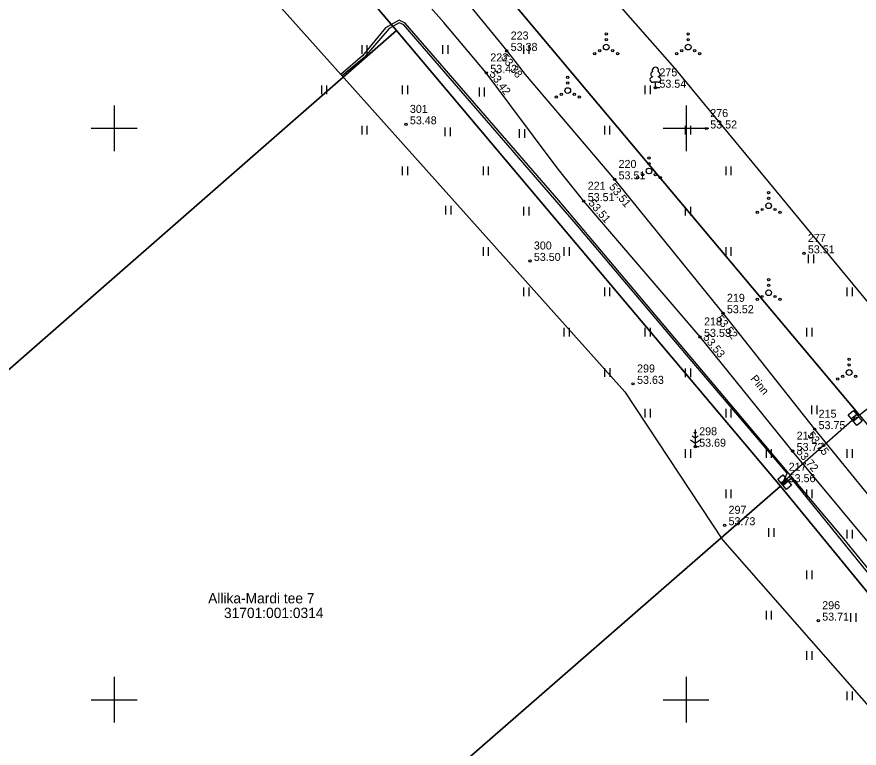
# Model space of a CAD drawing. Extents: x 538599 to 541973, y 6559689 to 6564516.
# Drawn here: x 540391.5 to 540465.1, y 6561345.8 to 6561409.8 of the extents above; entities that cross this region are included whole.
import ezdxf

# ---------------------------------------------------------------- set-up
doc = ezdxf.new("R2010")
doc.units = 0
for name, color, linetype in [('ELRAJATISMP', 7, 'Continuous'), ('HALJASTUS', 7, 'Continuous'), ('KORGUS-EH2000', 7, 'Continuous'), ('KPKAABEL', 7, 'Continuous'), ('MOOTKORG-EH2000', 7, 'Continuous'), ('MOOTMPUNKT', 7, 'Continuous'), ('MOOTNR', 7, 'Continuous'), ('MOOTPIIR', 7, 'Continuous'), ('MPKAABEL', 7, 'Continuous'), ('PIIR', 7, 'Continuous'), ('PUU', 7, 'Continuous'), ('TEE', 7, 'Continuous'), ('VORK', 7, 'Continuous')]:
    doc.layers.add(name, color=color, linetype=linetype)

msp = doc.modelspace()

# ---------------------------------------------------------------- linework, layer by layer
at = {"layer": 'ELRAJATISMP'}
for p, q in [((540464.943, 6561374.955), (540464.48, 6561374.578)), ((540465.114, 6561374.744), (540464.651, 6561374.367)), ((540458.768, 6561369.33), (540458.309, 6561368.949)), ((540458.941, 6561369.121), (540458.482, 6561368.74))]:
    msp.add_line(p, q, dxfattribs=at)
for points in [[(540464.652, 6561375.313), (540465.405, 6561374.386), (540464.942, 6561374.009), (540464.189, 6561374.936)], [(540458.473, 6561369.685), (540459.236, 6561368.766), (540458.777, 6561368.385), (540458.014, 6561369.304)]]:
    msp.add_lwpolyline(points, close=True, dxfattribs=at)
at = {"layer": 'HALJASTUS'}
for p, q in [((540421.648, 6561407.28), (540421.648, 6561406.519)), ((540422.103, 6561407.28), (540422.103, 6561406.519)), ((540428.719, 6561407.28), (540428.719, 6561406.519)), ((540429.175, 6561407.28), (540429.175, 6561406.519)), ((540435.791, 6561407.28), (540435.791, 6561406.519)), ((540436.246, 6561407.28), (540436.246, 6561406.519)), ((540418.113, 6561403.744), (540418.113, 6561402.983)), ((540418.568, 6561403.744), (540418.568, 6561402.983)), ((540425.184, 6561403.744), (540425.184, 6561402.983)), ((540425.639, 6561403.744), (540425.639, 6561402.983)), ((540431.902, 6561403.559), (540431.902, 6561402.797)), ((540432.357, 6561403.559), (540432.357, 6561402.797)), ((540446.397, 6561403.744), (540446.397, 6561402.983)), ((540446.852, 6561403.744), (540446.852, 6561402.983)), ((540421.648, 6561400.209), (540421.648, 6561399.447)), ((540422.103, 6561400.209), (540422.103, 6561399.447)), ((540428.921, 6561400.079), (540428.921, 6561399.318)), ((540429.376, 6561400.079), (540429.376, 6561399.318)), ((540435.422, 6561399.934), (540435.422, 6561399.173)), ((540435.877, 6561399.934), (540435.877, 6561399.173)), ((540442.862, 6561400.209), (540442.862, 6561399.447)), ((540443.317, 6561400.209), (540443.317, 6561399.447)), ((540449.933, 6561400.209), (540449.933, 6561399.447)), ((540450.388, 6561400.209), (540450.388, 6561399.447)), ((540425.184, 6561396.673), (540425.184, 6561395.912)), ((540425.639, 6561396.673), (540425.639, 6561395.912)), ((540432.255, 6561396.673), (540432.255, 6561395.912)), ((540432.71, 6561396.673), (540432.71, 6561395.912)), ((540453.468, 6561396.673), (540453.468, 6561395.912)), ((540453.923, 6561396.673), (540453.923, 6561395.912)), ((540428.983, 6561393.223), (540428.983, 6561392.462)), ((540429.438, 6561393.223), (540429.438, 6561392.462)), ((540435.791, 6561393.138), (540435.791, 6561392.376)), ((540436.246, 6561393.138), (540436.246, 6561392.376)), ((540449.933, 6561393.138), (540449.933, 6561392.376)), ((540450.388, 6561393.138), (540450.388, 6561392.376)), ((540432.255, 6561389.602), (540432.255, 6561388.841)), ((540432.71, 6561389.602), (540432.71, 6561388.841)), ((540439.326, 6561389.602), (540439.326, 6561388.841)), ((540439.781, 6561389.602), (540439.781, 6561388.841)), ((540453.468, 6561389.602), (540453.468, 6561388.841)), ((540453.923, 6561389.602), (540453.923, 6561388.841)), ((540460.691, 6561388.968), (540460.691, 6561388.207)), ((540461.146, 6561388.968), (540461.146, 6561388.207)), ((540435.791, 6561386.066), (540435.791, 6561385.305)), ((540436.246, 6561386.066), (540436.246, 6561385.305)), ((540442.862, 6561386.066), (540442.862, 6561385.305)), ((540443.317, 6561386.066), (540443.317, 6561385.305)), ((540464.075, 6561386.066), (540464.075, 6561385.305)), ((540464.53, 6561386.066), (540464.53, 6561385.305)), ((540439.326, 6561382.531), (540439.326, 6561381.77)), ((540439.781, 6561382.531), (540439.781, 6561381.77)), ((540446.397, 6561382.531), (540446.397, 6561381.77)), ((540446.852, 6561382.531), (540446.852, 6561381.77)), ((540460.539, 6561382.531), (540460.539, 6561381.77)), ((540460.994, 6561382.531), (540460.994, 6561381.77)), ((540442.882, 6561379.016), (540442.882, 6561378.255)), ((540443.338, 6561379.016), (540443.338, 6561378.255)), ((540449.933, 6561378.995), (540449.933, 6561378.234)), ((540450.388, 6561378.995), (540450.388, 6561378.234)), ((540446.397, 6561375.46), (540446.397, 6561374.699)), ((540446.852, 6561375.46), (540446.852, 6561374.699)), ((540453.468, 6561375.46), (540453.468, 6561374.699)), ((540453.923, 6561375.46), (540453.923, 6561374.699)), ((540460.981, 6561375.739), (540460.981, 6561374.977)), ((540461.436, 6561375.739), (540461.436, 6561374.977)), ((540449.933, 6561371.924), (540449.933, 6561371.163)), ((540450.388, 6561371.924), (540450.388, 6561371.163)), ((540457.004, 6561371.924), (540457.004, 6561371.163)), ((540457.459, 6561371.924), (540457.459, 6561371.163)), ((540464.075, 6561371.924), (540464.075, 6561371.163)), ((540464.53, 6561371.924), (540464.53, 6561371.163)), ((540453.468, 6561368.389), (540453.468, 6561367.628)), ((540453.923, 6561368.389), (540453.923, 6561367.628)), ((540460.539, 6561368.389), (540460.539, 6561367.628)), ((540460.994, 6561368.389), (540460.994, 6561367.628)), ((540457.224, 6561365.014), (540457.224, 6561364.253)), ((540457.679, 6561365.014), (540457.679, 6561364.253)), ((540464.075, 6561364.853), (540464.075, 6561364.092)), ((540464.53, 6561364.853), (540464.53, 6561364.092)), ((540460.539, 6561361.318), (540460.539, 6561360.557)), ((540460.994, 6561361.318), (540460.994, 6561360.557)), ((540457.004, 6561357.782), (540457.004, 6561357.021)), ((540457.459, 6561357.782), (540457.459, 6561357.021)), ((540464.388, 6561357.579), (540464.388, 6561356.817)), ((540464.843, 6561357.579), (540464.843, 6561356.817)), ((540460.539, 6561354.247), (540460.539, 6561353.486)), ((540460.994, 6561354.247), (540460.994, 6561353.486)), ((540464.075, 6561350.711), (540464.075, 6561349.95)), ((540464.53, 6561350.711), (540464.53, 6561349.95))]:
    msp.add_line(p, q, dxfattribs=at)
for centre, radius in [((540443.021, 6561408.263), 0.1), ((540443.021, 6561407.763), 0.1), ((540450.186, 6561408.263), 0.1), ((540450.186, 6561407.763), 0.1), ((540443.021, 6561407.113), 0.25), ((540450.186, 6561407.113), 0.25), ((540442.021, 6561406.538), 0.1), ((540442.456, 6561406.788), 0.1), ((540443.586, 6561406.788), 0.1), ((540444.021, 6561406.538), 0.1), ((540449.186, 6561406.538), 0.1), ((540449.621, 6561406.788), 0.1), ((540450.751, 6561406.788), 0.1), ((540451.186, 6561406.538), 0.1), ((540439.66, 6561404.457), 0.1), ((540439.66, 6561403.307), 0.25), ((540439.66, 6561403.957), 0.1), ((540438.66, 6561402.732), 0.1), ((540439.095, 6561402.982), 0.1), ((540440.225, 6561402.982), 0.1), ((540440.66, 6561402.732), 0.1), ((540446.762, 6561397.416), 0.1), ((540446.762, 6561396.916), 0.1), ((540446.762, 6561396.266), 0.25), ((540445.762, 6561395.691), 0.1), ((540446.197, 6561395.941), 0.1), ((540447.327, 6561395.941), 0.1), ((540447.762, 6561395.691), 0.1), ((540457.224, 6561394.371), 0.1), ((540457.224, 6561393.871), 0.1), ((540457.224, 6561393.221), 0.25), ((540456.224, 6561392.646), 0.1), ((540456.659, 6561392.896), 0.1), ((540457.789, 6561392.896), 0.1), ((540458.224, 6561392.646), 0.1), ((540457.224, 6561386.76), 0.1), ((540457.224, 6561385.61), 0.25), ((540457.224, 6561386.26), 0.1), ((540456.224, 6561385.035), 0.1), ((540456.659, 6561385.285), 0.1), ((540457.789, 6561385.285), 0.1), ((540458.224, 6561385.035), 0.1), ((540464.263, 6561379.783), 0.1), ((540464.263, 6561379.283), 0.1), ((540463.698, 6561378.308), 0.1), ((540464.263, 6561378.633), 0.25), ((540464.828, 6561378.308), 0.1), ((540463.263, 6561378.058), 0.1)]:
    msp.add_circle(centre, radius, dxfattribs=at)
at = {"layer": 'KORGUS-EH2000'}
for centre in [(540434.319, 6561406.773), (540432.536, 6561404.858), (540425.505, 6561400.353), (540451.769, 6561399.986), (540443.752, 6561395.534), (540441.058, 6561393.627), (540460.306, 6561389.06), (540436.345, 6561388.398), (540453.227, 6561383.82), (540451.227, 6561381.751), (540445.37, 6561377.639), (540461.243, 6561373.674), (540459.324, 6561371.761), (540453.37, 6561365.268), (540461.559, 6561356.917)]:
    msp.add_circle(centre, 0.1, dxfattribs=at)
at = {"layer": 'KPKAABEL'}
msp.add_lwpolyline([(540612.707, 6561251.641), (540589.754, 6561235.922), (540575.113, 6561226.32), (540574.309, 6561226.488), (540572.813, 6561227.652), (540566.988, 6561234.121), (540563.285, 6561239.03), (540553.802, 6561251.292), (540538.41, 6561271.219), (540529.488, 6561282.512), (540526.272, 6561286.879), (540510.559, 6561306.203), (540484.617, 6561338.574), (540463.547, 6561364.405), (540438.892, 6561393.697), (540425.441, 6561409.211), (540424.922, 6561409.461), (540423.725, 6561408.808), (540421.719, 6561406.34), (540419.82, 6561404.72)], dxfattribs=at)
at = {"layer": 'MOOTMPUNKT'}
for centre in [(540434.319, 6561406.773), (540432.536, 6561404.858), (540447.324, 6561403.552), (540425.505, 6561400.353), (540451.769, 6561399.986), (540443.752, 6561395.534), (540441.058, 6561393.627), (540460.306, 6561389.06), (540436.345, 6561388.398), (540453.227, 6561383.82), (540451.227, 6561381.751), (540445.37, 6561377.639), (540464.797, 6561374.661), (540461.243, 6561373.674), (540450.802, 6561372.138), (540459.324, 6561371.761), (540458.625, 6561369.035), (540453.37, 6561365.268), (540461.559, 6561356.917)]:
    msp.add_circle(centre, 0.1, dxfattribs=at)
at = {"layer": 'MOOTPIIR'}
for points in [[(540611.814, 6561347.628), (540600.551, 6561344.045), (540588.991, 6561338.307), (540579.507, 6561329.749), (540567.369, 6561324.711), (540557.296, 6561315.504), (540537.549, 6561303.29), (540525.23, 6561316.048), (540500.22, 6561345.282), (540476.488, 6561371.995), (540449.028, 6561405.277), (540428.792, 6561428.292), (540413.022, 6561448.218), (540405.096, 6561459.889), (540393.809, 6561473.145)], [(540384.887, 6561443.845), (540403.973, 6561422.469), (540424.304, 6561399.698), (540444.636, 6561376.927), (540453.177, 6561363.987), (540470.995, 6561343.689), (540492.689, 6561318.976), (540511.766, 6561294.341), (540521.974, 6561279.181), (540525.589, 6561267.954), (540536.495, 6561252.794), (540542.772, 6561231.926), (540526.603, 6561219.05), (540510.624, 6561213.468), (540498.26, 6561199.196), (540484.564, 6561192.98), (540479.618, 6561185.622), (540478.413, 6561178.328), (540490.461, 6561165.832), (540493.58, 6561162.597), (540531.105, 6561187.906), (540582.869, 6561222.817), (540621.742, 6561247.747)]]:
    msp.add_lwpolyline(points, dxfattribs=at)
at = {"layer": 'MPKAABEL'}
for points in [[(540496.217, 6561323.662), (540475.169, 6561349.87), (540465.845, 6561361.182), (540459.234, 6561369.371), (540458.445, 6561368.895), (540458.855, 6561369.82), (540450.374, 6561379.812), (540440.394, 6561391.62), (540426.571, 6561407.606), (540425.316, 6561409.047), (540424.926, 6561409.234), (540424.031, 6561408.75), (540421.855, 6561406.207), (540419.931, 6561404.596)], [(540464.749, 6561374.646), (540459.18, 6561369.75), (540458.445, 6561368.895)]]:
    msp.add_lwpolyline(points, dxfattribs=at)
at = {"layer": 'PIIR'}
for points in [[(540491.21, 6561183.5), (540566.07, 6561233.36), (540528.84, 6561281.85), (540494.34, 6561324.62), (540458.27, 6561368.69), (540424.68, 6561408.57), (540384.55, 6561455.73), (540346.17, 6561499.11), (540330.12, 6561517.14), (540337.36, 6561523.32), (540348.28, 6561532.96), (540364.11, 6561514.94), (540353.14, 6561505.27), (540391.51, 6561461.86), (540431.74, 6561414.74), (540465.17, 6561374.89), (540501.31, 6561330.86), (540535.92, 6561287.97), (540573.77, 6561238.75), (540640.63, 6561283.66), (540646.74, 6561272.89), (540499, 6561174.36)], [(540431.74, 6561414.74), (540500.82, 6561475.34), (540537.11, 6561431.06), (540465.17, 6561374.89)], [(540309.49, 6561390.29), (540384.55, 6561455.73), (540424.68, 6561408.57), (540350.66, 6561343.77)], [(540350.66, 6561343.77), (540424.68, 6561408.57), (540458.27, 6561368.69), (540384.73, 6561304.57)], [(540384.73, 6561304.57), (540458.27, 6561368.69), (540494.34, 6561324.62), (540422.29, 6561261.69)]]:
    msp.add_lwpolyline(points, close=True, dxfattribs=at)
at = {"layer": 'PUU'}
for p, q in [((540447.564, 6561404.027), (540447.084, 6561404.027)), ((540447.324, 6561403.552), (540447.324, 6561404.027)), ((540447.704, 6561403.552), (540447.324, 6561403.552)), ((540450.802, 6561373.288), (540450.678, 6561373.371)), ((540450.802, 6561373.638), (540450.802, 6561372.138)), ((540450.926, 6561373.371), (540450.802, 6561373.288)), ((540450.378, 6561372.727), (540450.802, 6561372.445)), ((540450.802, 6561372.888), (540450.535, 6561373.066)), ((540451.069, 6561373.066), (540450.802, 6561372.888)), ((540450.802, 6561372.445), (540451.226, 6561372.727)), ((540451.162, 6561372.138), (540450.802, 6561372.138))]:
    msp.add_line(p, q, dxfattribs=at)
for centre, radius, start, end in [((540447.154, 6561404.725), 0.233, 109.02174, 253.14154), ((540447.324, 6561405.072), 0.277, 332.5799, 207.4201), ((540447.494, 6561404.725), 0.233, 286.85082, 70.98591), ((540447.087, 6561404.264), 0.238, 90.0016, 269.3953), ((540447.561, 6561404.264), 0.238, 270.6047, 89.9984)]:
    msp.add_arc(centre, radius, start, end, dxfattribs=at)
at = {"layer": 'TEE'}
for points in [[(540488.154, 6561336.579), (540478.587, 6561348.431), (540467.854, 6561361.491), (540459.324, 6561371.761), (540451.227, 6561381.751), (540441.058, 6561393.627), (540438.742, 6561396.541), (540432.536, 6561404.858), (540428.826, 6561409.256), (540422.187, 6561416.809), (540412.686, 6561428.773), (540402.743, 6561440.044), (540395.606, 6561447.094), (540392.506, 6561450.435), (540382.51, 6561461.307)], [(540388.6, 6561459.282), (540394.606, 6561452.944), (540404.957, 6561441.5), (540414.409, 6561430.917), (540424.761, 6561418.487), (540434.319, 6561406.773), (540435.946, 6561404.714), (540443.752, 6561395.534), (540453.227, 6561383.82), (540461.243, 6561373.674), (540469.957, 6561362.956), (540476.197, 6561354.987), (540480.237, 6561350.173), (540490.343, 6561338.333)]]:
    msp.add_lwpolyline(points, dxfattribs=at)
at = {"layer": 'VORK'}
for p, q in [((540400, 6561402), (540400, 6561398)), ((540450, 6561402), (540450, 6561398)), ((540398, 6561400), (540402, 6561400)), ((540448, 6561400), (540452, 6561400)), ((540400, 6561352), (540400, 6561348)), ((540450, 6561352), (540450, 6561348)), ((540398, 6561350), (540402, 6561350)), ((540448, 6561350), (540452, 6561350))]:
    msp.add_line(p, q, dxfattribs=at)

# ---------------------------------------------------------------- texts
at = {"layer": 'KORGUS-EH2000'}
for s, rotation, p in [('53.38', 308.31584, (540433.771, 6561406.169)), ('53.42', 306.73046, (540432.771, 6561404.716)), ('53.51', 308.96805, (540443.226, 6561394.848)), ('53.51', 310.57228, (540441.424, 6561393.431)), ('53.52', 308.31103, (540452.583, 6561383.313)), ('53.53', 309.02513, (540451.455, 6561381.67)), ('53.75', 309.11197, (540460.559, 6561373.126)), ('53.72', 309.71216, (540459.606, 6561371.673))]:
    msp.add_text(s, height=0.7, rotation=rotation, dxfattribs=at).set_placement(p)
for s, p in [('53.48', (540425.855, 6561400.353)), ('53.52', (540452.119, 6561399.986)), ('53.51', (540460.656, 6561389.06)), ('53.51', (540460.656, 6561389.06)), ('53.50', (540436.695, 6561388.398)), ('53.63', (540445.72, 6561377.639)), ('53.73', (540453.72, 6561365.268)), ('53.71', (540461.909, 6561356.917))]:
    msp.add_text(s, height=0.7, dxfattribs=at).set_placement(p)
at = {"layer": 'MOOTKORG-EH2000'}
for s, p in [('53.38', (540434.669, 6561406.773)), ('53.42', (540432.886, 6561404.858)), ('53.54', (540447.674, 6561403.552)), ('53.48', (540425.855, 6561400.353)), ('53.52', (540452.119, 6561399.986)), ('53.51', (540444.102, 6561395.534)), ('53.51', (540441.408, 6561393.627)), ('53.51', (540460.656, 6561389.06)), ('53.50', (540436.695, 6561388.398)), ('53.52', (540453.577, 6561383.82)), ('53.53', (540451.577, 6561381.751)), ('53.63', (540445.72, 6561377.639)), ('53.75', (540461.593, 6561373.674)), ('53.69', (540451.152, 6561372.138)), ('53.72', (540459.674, 6561371.761)), ('53.56', (540458.975, 6561369.035)), ('53.73', (540453.72, 6561365.268)), ('53.71', (540461.909, 6561356.917))]:
    msp.add_text(s, height=0.7, dxfattribs=at).set_placement(p)
at = {"layer": 'MOOTNR'}
for s, p in [('223', (540434.669, 6561407.773)), ('222', (540432.886, 6561405.858)), ('275', (540447.674, 6561404.552)), ('301', (540425.855, 6561401.353)), ('276', (540452.119, 6561400.986)), ('220', (540444.102, 6561396.534)), ('221', (540441.408, 6561394.627)), ('277', (540460.656, 6561390.06)), ('300', (540436.695, 6561389.398)), ('219', (540453.577, 6561384.82)), ('218', (540451.577, 6561382.751)), ('299', (540445.72, 6561378.639)), ('215', (540461.593, 6561374.674)), ('298', (540451.152, 6561373.138)), ('214', (540459.674, 6561372.761)), ('217', (540458.975, 6561370.035)), ('297', (540453.72, 6561366.268)), ('296', (540461.909, 6561357.917))]:
    msp.add_text(s, height=0.7, dxfattribs=at).set_placement(p)
at = {"layer": 'PIIR'}
for s, p in [('Allika-Mardi tee 7', (540408.217, 6561358.429)), ('31701:001:0314', (540409.598, 6561357.146))]:
    msp.add_text(s, height=0.9, rotation=0, dxfattribs=at).set_placement(p)
at = {"layer": 'TEE'}
msp.add_text('Pinn', height=0.7, rotation=309.02513, dxfattribs=at).set_placement((540455.595, 6561378.07))

doc.saveas('drawing.dxf')
